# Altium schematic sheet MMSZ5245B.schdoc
size 127 x 101 mm
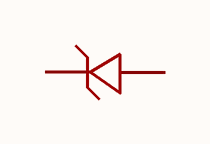
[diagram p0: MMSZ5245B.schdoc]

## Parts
ZD?  mmsz5245b_c2126  [SOD-123_L2.8-W1.8-LS3.7-RD]  (value not drawn)

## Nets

Not connected (* = marked no-connect by the designer): ZD? 1(K) 2(A)

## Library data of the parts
ZD? = mmsz5245b_c2126: 二极管配置:1个独立式;稳压值(标称值):15V;稳压值(范围):14.25V~15.75V;耗散功率(Pd):350mW;; Manufacturer: CJ(江苏长电/长晶); AddInBom: yes; ModelId: 7884390a25fb4c08947731ebfba7e3f8; ModelTransform: 144.8816,62.992,0,0,0,0,0,0,0; Diode Configuration: 1个独立式; Zener Voltage(Nom): 15V; Reverse Leakage Current (Ir): 100nA; Pd - Power Dissipation: 350mW; Impedance(Zzt): 16Ω; Impedance(Zzk): 600Ω; Operating Junction Temperature Range: -65℃~+150℃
